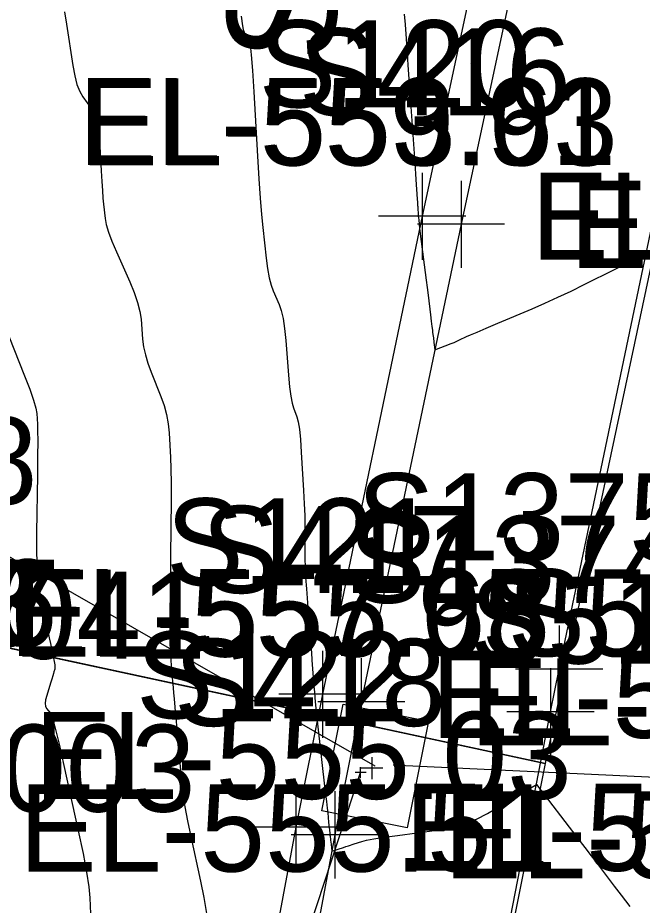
# Model space of a CAD drawing. Extents: x 1724534 to 1727318, y 657156 to 660047.
# Drawn here: x 1725433.66 to 1725462.33, y 659000.27 to 659041.04 of the extents above; entities that cross this region are included whole.
import ezdxf

# ---------------------------------------------------------------- set-up
doc = ezdxf.new("R2010")
doc.units = 0
for name, color, linetype in [('SURVEY - CONTOURS - Intermediate with optional Text', 7, 'Continuous'), ('SURVEY - DRAINAGE - Area Shapes', 7, 'Continuous'), ('SURVEY - DRAINAGE - Storm Sewer', 7, 'Continuous'), ('SURVEY - DRAINAGE - Storm Sewer - Points - Locators', 7, 'Continuous'), ('SURVEY - DRAINAGE - Storm Sewer - Points - Numbers', 7, 'Continuous'), ('SURVEY - DRAINAGE - Storm Sewer Text', 7, 'Continuous'), ('SURVEY - DTM - Breaklines', 7, 'Continuous'), ('SURVEY - DTM - Breaklines - Points - Elevations', 7, 'Continuous'), ('SURVEY - DTM - Breaklines - Points - Locators', 7, 'Continuous'), ('SURVEY - DTM - Breaklines - Points - Numbers', 7, 'Continuous'), ('SURVEY - MISCELLANEOUS - Bottom of MH and CB', 7, 'Continuous'), ('SURVEY - MISCELLANEOUS - Bottom of MH and CB - Points - Numbers', 7, 'Continuous'), ('SURVEY - NON-TRANSPORTATION - Features - Points - Elevations', 7, 'Continuous'), ('SURVEY - NON-TRANSPORTATION - Features - Points - Numbers', 7, 'Continuous'), ('SURVEY - TRANSPORTATION - Features', 7, 'Continuous'), ('SURVEY - TRANSPORTATION - Features - Points - Elevations', 7, 'Continuous'), ('SURVEY - TRANSPORTATION - Features - Points - Locators', 7, 'Continuous'), ('SURVEY - TRANSPORTATION - Features - Points - Numbers', 7, 'Continuous'), ('SURVEY - TRANSPORTATION - Roads', 7, 'Continuous'), ('SURVEY - TRANSPORTATION - Roads - Points - Locators', 7, 'Continuous'), ('SURVEY - TRANSPORTATION - Roads - Points - Numbers', 7, 'Continuous'), ('SURVEY - VEGETATION - Features with Text', 7, 'Continuous')]:
    doc.layers.add(name, color=color, linetype=linetype)

msp = doc.modelspace()

# ---------------------------------------------------------------- linework, layer by layer
at = {"layer": 'SURVEY - CONTOURS - Intermediate with optional Text'}
for points in [[(1725435.808, 659041.308), (1725435.894, 659040.746), (1725436.184, 659038.846), (1725436.271, 659038.37), (1725436.376, 659037.972), (1725436.5, 659037.65), (1725436.641, 659037.406), (1725437.043, 659036.856), (1725437.179, 659036.61), (1725437.284, 659036.286), (1725437.359, 659035.882), (1725437.404, 659035.4), (1725437.484, 659034.009), (1725437.514, 659033.522), (1725437.542, 659033.104), (1725437.57, 659032.754), (1725437.598, 659032.474), (1725437.669, 659031.817), (1725437.722, 659031.537), (1725437.825, 659031.189), (1725437.979, 659030.773), (1725438.185, 659030.288), (1725438.8, 659028.907), (1725439.006, 659028.411), (1725439.16, 659027.959), (1725439.264, 659027.552), (1725439.317, 659027.188), (1725439.391, 659026.279), (1725439.436, 659025.928), (1725439.516, 659025.558), (1725439.63, 659025.169), (1725439.779, 659024.76), (1725440.223, 659023.645), (1725440.372, 659023.227), (1725440.485, 659022.807), (1725440.563, 659022.387), (1725440.605, 659021.966), (1725440.669, 659020.842), (1725440.688, 659020.33), (1725440.698, 659019.639), (1725440.697, 659018.769), (1725440.688, 659017.718), (1725440.648, 659014.677), (1725440.637, 659013.655), (1725440.634, 659012.87), (1725440.637, 659012.321), (1725440.649, 659012.009), (1725440.689, 659011.491), (1725440.703, 659011.307), (1725440.716, 659011.143), (1725440.727, 659010.998), (1725440.736, 659010.874), (1725440.76, 659010.567), (1725440.771, 659010.431), (1725440.787, 659010.25), (1725440.807, 659010.026), (1725440.831, 659009.758), (1725440.903, 659008.984), (1725440.927, 659008.72), (1725440.947, 659008.506), (1725440.962, 659008.343), (1725440.972, 659008.231), (1725440.994, 659008), (1725441.005, 659007.87), (1725441.025, 659007.655), (1725441.051, 659007.353), (1725441.086, 659006.965), (1725441.187, 659005.817), (1725441.241, 659005.344), (1725441.328, 659004.788), (1725441.448, 659004.147), (1725441.6, 659003.423), (1725442.049, 659001.379), (1725442.2, 659000.623), (1725442.316, 658999.886)], [(1725443.912, 659041.119), (1725443.982, 659040.662), (1725444.011, 659040.504), (1725444.046, 659040.371), (1725444.087, 659040.263), (1725444.134, 659040.182), (1725444.268, 659039.999), (1725444.32, 659039.8), (1725444.375, 659039.34), (1725444.434, 659038.619), (1725444.496, 659037.638), (1725444.667, 659034.674), (1725444.73, 659033.636), (1725444.791, 659032.744), (1725444.851, 659031.999), (1725444.909, 659031.401), (1725445.061, 659030.001), (1725445.124, 659029.513), (1725445.199, 659029.098), (1725445.285, 659028.757), (1725445.382, 659028.488), (1725445.657, 659027.871), (1725445.754, 659027.593), (1725445.836, 659027.225), (1725445.905, 659026.765), (1725445.961, 659026.213), (1725446.09, 659024.622), (1725446.14, 659024.08), (1725446.194, 659023.649), (1725446.25, 659023.328), (1725446.311, 659023.117), (1725446.476, 659022.702), (1725446.535, 659022.483), (1725446.588, 659022.139), (1725446.635, 659021.67), (1725446.675, 659021.075), (1725446.775, 659019.32), (1725446.808, 659018.705), (1725446.83, 659018.177), (1725446.841, 659017.735), (1725446.842, 659017.38), (1725446.832, 659016.547), (1725446.834, 659016.204), (1725446.847, 659015.799), (1725446.873, 659015.331), (1725446.91, 659014.802), (1725447.026, 659013.308), (1725447.067, 659012.776), (1725447.104, 659012.302), (1725447.136, 659011.885), (1725447.164, 659011.525), (1725447.257, 659010.328), (1725447.279, 659010.051), (1725447.299, 659009.811), (1725447.318, 659009.606), (1725447.398, 659008.737), (1725447.778, 659005.469), (1725447.827, 659005.042), (1725447.863, 659004.722), (1725447.886, 659004.507), (1725447.929, 659004.078), (1725447.956, 659003.821), (1725447.964, 659003.741), (1725447.969, 659003.694), (1725447.979, 659003.61), (1725447.983, 659003.576), (1725447.992, 659003.491), (1725447.998, 659003.44), (1725448.013, 659003.295), (1725448.019, 659003.239), (1725448.025, 659003.181), (1725448.039, 659003.055), (1725448.072, 659002.748), (1725448.609, 659002.925), (1725448.727, 659002.964), (1725448.849, 659003.004), (1725449.106, 659003.088), (1725449.461, 659003.203), (1725449.662, 659003.253), (1725450.001, 659003.315), (1725450.476, 659003.389), (1725451.087, 659003.476), (1725452.901, 659003.724), (1725453.556, 659003.841), (1725454.162, 659004.007), (1725454.717, 659004.219), (1725455.223, 659004.48), (1725457.467, 659005.81), (1725459.332, 659003.391), (1725459.695, 659002.919), (1725459.987, 659002.539), (1725460.207, 659002.252), (1725460.355, 659002.057), (1725460.807, 659001.458), (1725461.042, 659001.149), (1725461.361, 659000.732), (1725461.762, 659000.209)], [(1725451.405, 659041.204), (1725451.438, 659040.73), (1725451.53, 659039.406), (1725451.568, 659038.864), (1725451.612, 659038.229), (1725451.88, 659034.373), (1725451.933, 659033.611), (1725451.996, 659032.706), (1725452.006, 659032.564), (1725452.014, 659032.459), (1725452.017, 659032.417), (1725452.02, 659032.367), (1725452.023, 659032.311), (1725452.027, 659032.247), (1725452.037, 659032.069), (1725452.042, 659031.999), (1725452.048, 659031.925), (1725452.055, 659031.846), (1725452.064, 659031.761), (1725452.108, 659031.356), (1725452.322, 659029.692), (1725452.367, 659029.338), (1725452.411, 659028.988), (1725452.454, 659028.643), (1725452.496, 659028.302), (1725452.606, 659027.399), (1725452.643, 659027.094), (1725452.672, 659026.857), (1725452.693, 659026.687), (1725452.706, 659026.586), (1725452.728, 659026.405), (1725452.737, 659026.336), (1725452.745, 659026.266), (1725452.754, 659026.195), (1725452.763, 659026.122), (1725452.804, 659025.779), (1725453.556, 659026.073), (1725453.686, 659026.127), (1725453.813, 659026.182), (1725453.937, 659026.238), (1725454.267, 659026.39), (1725454.448, 659026.471), (1725454.747, 659026.601), (1725455.162, 659026.779), (1725455.694, 659027.005), (1725457.267, 659027.673), (1725457.86, 659027.93), (1725458.457, 659028.2), (1725459.059, 659028.484), (1725459.666, 659028.781), (1725462.508, 659030.196)], [(1725433.248, 659026.404), (1725433.971, 659024.589), (1725434.209, 659023.97), (1725434.383, 659023.475), (1725434.491, 659023.104), (1725434.534, 659022.857), (1725434.562, 659022.363), (1725434.57, 659022.078), (1725434.572, 659021.592), (1725434.568, 659020.906), (1725434.558, 659020.019), (1725434.524, 659017.387), (1725434.523, 659016.474), (1725434.547, 659015.708), (1725434.595, 659015.089), (1725434.666, 659014.618), (1725434.891, 659013.557), (1725434.97, 659013.18), (1725435.041, 659012.845), (1725435.103, 659012.551), (1725435.157, 659012.299), (1725435.287, 659011.681), (1725435.328, 659011.473), (1725435.353, 659011.31), (1725435.362, 659011.192), (1725435.356, 659011.12), (1725435.316, 659010.99), (1725435.295, 659010.92), (1725435.261, 659010.81), (1725435.215, 659010.659), (1725435.157, 659010.466), (1725434.985, 659009.898), (1725434.936, 659009.702), (1725434.92, 659009.538), (1725434.935, 659009.408), (1725434.983, 659009.31), (1725435.153, 659009.094), (1725435.24, 659008.882), (1725435.372, 659008.41), (1725435.551, 659007.676), (1725435.775, 659006.681), (1725436.435, 659003.681), (1725436.654, 659002.645), (1725436.815, 659001.787), (1725436.918, 659001.107), (1725436.964, 659000.606), (1725437.01, 658999.506)]]:
    msp.add_lwpolyline(points, dxfattribs=at)
at = {"layer": 'SURVEY - DRAINAGE - Area Shapes'}
for points in [[(1725457.865, 659006.777), (1725413.857, 659016.262), (1725297.605, 659050.843), (1725314.042, 659296.608), (1725386.76, 659493.901), (1725483.401, 659755.229), (1725623.949, 659732.704), (1725676.22, 659724.326), (1725634.82, 659466.017), (1725543.324, 659353.721), (1725499.683, 659185.923), (1725479.088, 659106.738)], [(1725413.857, 659016.262), (1725457.865, 659006.777), (1725450.771, 658971.313), (1725440.158, 658905.178), (1725430.327, 658830.786), (1725434.818, 658762.279), (1725443.395, 658712.742), (1725438.076, 658666.381), (1725439.858, 658660.363), (1725446.978, 658655.619), (1725466.254, 658652.836), (1725462.782, 658619.36), (1725332.114, 658635.492), (1725320.808, 658709.212), (1725296.636, 658734.956), (1725279.099, 658753.634), (1725289.919, 658934.648), (1725297.605, 659050.843)]]:
    msp.add_lwpolyline(points, close=True, dxfattribs=at)
at = {"layer": 'SURVEY - DRAINAGE - Storm Sewer'}
for p, q in [((1725450.064, 659006.662), (1725450.064, 659006.662)), ((1725451.141, 659006.707), (1725524.546, 659003.293)), ((1725419.597, 658915.715), (1725449.396, 659006.368))]:
    msp.add_line(p, q, dxfattribs=at)
msp.add_lwpolyline([(1725451.538, 659003.82), (1725447.615, 659004.6), (1725448.59, 659009.504), (1725452.513, 659008.724), (1725451.538, 659003.82)], dxfattribs=at)
at = {"layer": 'SURVEY - DRAINAGE - Storm Sewer - Points - Locators'}
for p, q in [((1725449.396, 659006.118), (1725449.396, 659006.618)), ((1725451.391, 659006.707), (1725450.891, 659006.707)), ((1725451.141, 659006.457), (1725451.141, 659006.957)), ((1725451.141, 659006.707), (1725451.141, 659006.707)), ((1725451.141, 659006.707), (1725451.141, 659006.707)), ((1725449.646, 659006.368), (1725449.146, 659006.368)), ((1725449.396, 659006.368), (1725449.396, 659006.368)), ((1725449.396, 659006.368), (1725449.396, 659006.368))]:
    msp.add_line(p, q, dxfattribs=at)
at = {"layer": 'SURVEY - DRAINAGE - Storm Sewer Text'}
msp.add_lwpolyline([(1725450.064, 659006.662), (1725394.638, 659038.38), (1725401.858, 659097.984)], dxfattribs=at)
at = {"layer": 'SURVEY - DTM - Breaklines'}
msp.add_lwpolyline([(1725504.884, 659250.966), (1725498.725, 659226.793), (1725492.704, 659202.503), (1725486.609, 659178.27), (1725480.544, 659153.955), (1725474.624, 659129.616), (1725468.741, 659105.278), (1725462.975, 659080.964), (1725457.482, 659056.509), (1725452.226, 659031.922), (1725447.641, 659009.959), (1725446.425, 659003.851), (1725441.811, 658979.15), (1725437.527, 658954.376), (1725432.503, 658922.481), (1725434.197, 658921.722)], dxfattribs=at)
at = {"layer": 'SURVEY - DTM - Breaklines - Points - Locators'}
for p, q in [((1725452.226, 659033.922), (1725452.226, 659029.922)), ((1725454.226, 659031.922), (1725450.226, 659031.922)), ((1725447.641, 659011.959), (1725447.641, 659007.959)), ((1725449.641, 659009.959), (1725445.641, 659009.959)), ((1725446.425, 659005.851), (1725446.425, 659001.851)), ((1725448.425, 659003.851), (1725444.425, 659003.851))]:
    msp.add_line(p, q, dxfattribs=at)
at = {"layer": 'SURVEY - MISCELLANEOUS - Bottom of MH and CB'}
for p, q in [((1725449.924, 659006.065), (1725449.924, 659007.065)), ((1725450.424, 659006.565), (1725449.424, 659006.565)), ((1725449.924, 659006.565), (1725449.924, 659006.565)), ((1725449.924, 659006.565), (1725449.924, 659006.565))]:
    msp.add_line(p, q, dxfattribs=at)
at = {"layer": 'SURVEY - TRANSPORTATION - Features'}
msp.add_lwpolyline([(1725506.673, 659250.514), (1725500.512, 659226.334), (1725494.493, 659202.049), (1725488.389, 659177.819), (1725482.327, 659153.516), (1725476.395, 659129.191), (1725470.514, 659104.862), (1725464.748, 659080.55), (1725459.259, 659056.109), (1725454.008, 659031.549), (1725449.429, 659009.612), (1725448.213, 659003.504), (1725443.603, 658978.829), (1725439.325, 658954.082), (1725434.304, 658922.209), (1725434.197, 658921.722)], dxfattribs=at)
at = {"layer": 'SURVEY - TRANSPORTATION - Features - Points - Locators'}
for p, q in [((1725454.008, 659033.549), (1725454.008, 659029.549)), ((1725456.008, 659031.549), (1725452.008, 659031.549)), ((1725449.429, 659011.612), (1725449.429, 659007.612)), ((1725451.429, 659009.612), (1725447.429, 659009.612)), ((1725448.213, 659005.504), (1725448.213, 659001.504)), ((1725450.213, 659003.504), (1725446.213, 659003.504))]:
    msp.add_line(p, q, dxfattribs=at)
at = {"layer": 'SURVEY - TRANSPORTATION - Roads'}
msp.add_lwpolyline([(1725435.76, 658873.112), (1725439.371, 658898.842), (1725439.657, 658900.819), (1725445.023, 658936.389), (1725447.926, 658954.139), (1725448.261, 658956.109), (1725453.558, 658985.616), (1725453.93, 658987.58), (1725458.117, 659009.159), (1725458.517, 659011.117), (1725466.292, 659048.286), (1725466.718, 659050.238), (1725471.114, 659069.737), (1725478.393, 659100.872), (1725479.306, 659104.764), (1725484.9, 659128.087), (1725485.373, 659130.029), (1725489.666, 659147.5), (1725494.922, 659168.852), (1725495.411, 659170.791), (1725504.745, 659207.606), (1725509.226, 659225.033), (1725509.717, 659226.971)], dxfattribs=at)
at = {"layer": 'SURVEY - TRANSPORTATION - Roads - Points - Locators'}
for p, q in [((1725458.517, 659013.117), (1725458.517, 659009.117)), ((1725460.517, 659011.117), (1725456.517, 659011.117)), ((1725458.117, 659011.159), (1725458.117, 659007.159)), ((1725460.117, 659009.159), (1725456.117, 659009.159))]:
    msp.add_line(p, q, dxfattribs=at)

# ---------------------------------------------------------------- texts
at = {"layer": 'SURVEY - DRAINAGE - Storm Sewer - Points - Numbers'}
for s, p in [('S2041', (1725426.822, 659011.59)), ('S5109', (1725456.141, 659011.707)), ('S5107', (1725454.396, 659011.368))]:
    msp.add_text(s, height=4, dxfattribs=at).set_placement(p)
at = {"layer": 'SURVEY - DTM - Breaklines - Points - Elevations'}
for s, p in [('EL-559.91', (1725436.444, 659034.269)), ('EL-550.98', (1725457.226, 659029.922)), ('EL-557.95', (1725433.274, 659011.717)), ('EL-551.95', (1725452.641, 659007.959)), ('EL-555.03', (1725434.417, 659005.151)), ('EL-552.22', (1725451.425, 659001.851))]:
    msp.add_text(s, height=4, dxfattribs=at).set_placement(p)
at = {"layer": 'SURVEY - DTM - Breaklines - Points - Numbers'}
for s, p in [('S120', (1725444.717, 659036.922)), ('S121', (1725440.463, 659014.959)), ('S122', (1725439.089, 659008.851))]:
    msp.add_text(s, height=4, dxfattribs=at).set_placement(p)
at = {"layer": 'SURVEY - MISCELLANEOUS - Bottom of MH and CB - Points - Numbers'}
msp.add_text('S8003', height=4, dxfattribs=at).set_placement((1725426.349, 659004.565))
at = {"layer": 'SURVEY - NON-TRANSPORTATION - Features - Points - Elevations'}
for s, p in [('EL-553.63', (1725436.524, 659034.252)), ('EL-555.68', (1725433.421, 659011.689)), ('EL-555.03', (1725434.417, 659005.151)), ('EL-555.03', (1725434.417, 659005.151)), ('EL-555.03', (1725434.417, 659005.151)), ('EL-555.51', (1725433.713, 659001.816))]:
    msp.add_text(s, height=4, dxfattribs=at).set_placement(p)
at = {"layer": 'SURVEY - NON-TRANSPORTATION - Features - Points - Numbers'}
for s, p in [('S1618', (1725419.086, 659018.689)), ('S1616', (1725420.019, 659012.151)), ('S1617', (1725420.129, 659012.151)), ('S668', (1725422.034, 659012.151))]:
    msp.add_text(s, height=4, dxfattribs=at).set_placement(p)
at = {"layer": 'SURVEY - TRANSPORTATION - Features - Points - Elevations'}
for s, p in [('EL-550.75', (1725459.008, 659029.549)), ('EL-551.71', (1725454.429, 659007.612)), ('EL-551.97', (1725453.213, 659001.504))]:
    msp.add_text(s, height=4, dxfattribs=at).set_placement(p)
at = {"layer": 'SURVEY - TRANSPORTATION - Features - Points - Numbers'}
for s, p in [('S416', (1725446.562, 659036.549)), ('S417', (1725442.093, 659014.612)), ('S418', (1725440.83, 659008.504))]:
    msp.add_text(s, height=4, dxfattribs=at).set_placement(p)
at = {"layer": 'SURVEY - TRANSPORTATION - Roads - Points - Numbers'}
for s, p in [('S1375', (1725449.229, 659016.117)), ('S1374', (1725448.829, 659014.159))]:
    msp.add_text(s, height=4, dxfattribs=at).set_placement(p)
at = {"layer": 'SURVEY - VEGETATION - Features with Text'}
msp.add_text('GRASS', height=5, rotation=262.3562, dxfattribs=at).set_placement((1725446.126, 659062.682))

doc.saveas('drawing.dxf')
